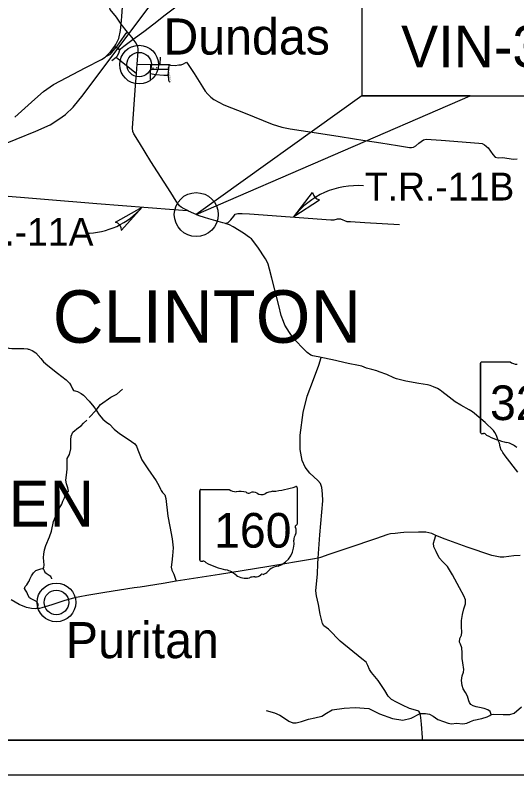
# Model space of a CAD drawing. Extents: x -22 to 431, y -18 to 160.
# Drawn here: x -18.95 to -17.504, y 22.164 to 24.356 of the extents above; entities that cross this region are included whole.
import ezdxf

# ---------------------------------------------------------------- set-up
doc = ezdxf.new("R2010")
doc.units = 0
for name, color, linetype in [('GM_X_Adjacent_County', 7, 'Continuous'), ('GM_X_Adjacent_County_Text', 7, 'Continuous'), ('GM_X_Airport_Location_Class_2', 7, 'Continuous'), ('GM_X_County_Road', 7, 'Continuous'), ('GM_X_County_Road_Text', 7, 'Continuous'), ('GM_X_County_ROW', 7, 'Continuous'), ('GM_X_County_Subdivision', 7, 'Continuous'), ('GM_X_Interstate_Location', 7, 'Continuous'), ('GM_X_Minor_Lake', 7, 'Continuous'), ('GM_X_Minor_River_Text', 7, 'Continuous'), ('GM_X_Section', 7, 'Continuous'), ('GM_X_State_Location', 7, 'Continuous'), ('GM_X_Township_Road', 7, 'Continuous'), ('GM_X_Township_ROW', 7, 'Continuous')]:
    doc.layers.add(name, color=color, linetype=linetype)

msp = doc.modelspace()

# ---------------------------------------------------------------- linework, layer by layer
at = {"layer": 'GM_X_Adjacent_County'}
for p, q in [((-18.147, 23.7739), (-18.0927, 23.8445)), ((-18.0927, 23.8445), (-18.0928, 23.8444)), ((-18.073, 23.8229), (-18.147, 23.7739)), ((-18.073, 23.8229), (-18.073, 23.8229)), ((-18.661, 23.7592), (-18.5836, 23.8025)), ((-18.5836, 23.8025), (-18.643, 23.7362)), ((-18.661, 23.7592), (-18.661, 23.7592)), ((-18.643, 23.7362), (-18.6429, 23.7362))]:
    msp.add_line(p, q, dxfattribs=at)
msp.add_circle((-18.428, 23.781), 0.0633, dxfattribs=at)
for centre, radius, start, end in [((-17.9649, 23.636), 0.2284, 85.1742, 142.8783), ((-18.0664, 23.8487), 0.0266, 189.1962, 255.8769), ((-18.7473, 23.9426), 0.2154, 269.9591, 319.4479), ((-18.6695, 23.7339), 0.0266, 4.907, 71.5877)]:
    msp.add_arc(centre, radius, start, end, dxfattribs=at)
at = {"layer": 'GM_X_Adjacent_County_Text'}
for points in [[(-18.6444, 24.3307), (-18.6582, 24.3505), (-18.6757, 24.3727), (-18.6795, 24.385), (-18.6947, 24.445), (-18.6988, 24.4658), (-18.6979, 24.4791), (-18.6949, 24.4873), (-18.6703, 24.5281), (-18.6438, 24.5713), (-18.6356, 24.5844), (-18.6327, 24.5869), (-18.6291, 24.5876)], [(-18.6094, 24.287), (-18.5787, 24.3092), (-18.5505, 24.3315), (-18.518, 24.3574), (-18.4605, 24.3995), (-18.4433, 24.4142), (-18.4205, 24.4347), (-18.4028, 24.4517), (-18.3964, 24.4589), (-18.3859, 24.4643), (-18.3672, 24.4727), (-18.3366, 24.484), (-18.3213, 24.4913), (-18.31, 24.5002), (-18.2964, 24.5094), (-18.2833, 24.5163), (-18.2703, 24.5193), (-18.2595, 24.5215), (-18.252, 24.5266), (-18.2431, 24.5343), (-18.2431, 24.5343)]]:
    msp.add_lwpolyline(points, dxfattribs=at)
at = {"layer": 'GM_X_Airport_Location_Class_2'}
for p, q in [((-17.608, 23.3522), (-17.608, 23.152)), ((-17.608, 23.152), (-17.608, 23.3522)), ((-17.608, 23.152), (-17.608, 23.3522)), ((-17.6052, 23.3556), (-17.5232, 23.3556)), ((-18.4173, 22.9841), (-18.4173, 22.784)), ((-18.4173, 22.784), (-18.4173, 22.9841)), ((-18.4173, 22.784), (-18.4173, 22.9841)), ((-18.4146, 22.9876), (-18.3325, 22.9876)), ((-18.1372, 22.9925), (-18.1372, 22.8878)), ((-18.1372, 22.8879), (-18.1372, 22.8878))]:
    msp.add_line(p, q, dxfattribs=at)
for centre, major_axis, start_param, end_param in [((-17.6048, 23.3526), (0.00325, 0), 1.712693, 3.28349), ((-17.5036, 23.3788), (0.0315, 0), 4.042523, 4.731795), ((-17.6047, 23.1516), (0.00327, 0), 3.00124, 4.508301), ((-17.6042, 23.1721), (0.025, 0), 4.665946, 4.897461), ((-17.5991, 23.1405), (0.00901, 0), 0.519207, 1.627899), ((-17.4854, 23.3203), (0.2145, 0), 4.195997, 4.488961), ((-17.5493, 23.0621), (0.0671, 0), 0.823519, 1.323587), ((-18.237, 23.2604), (0.2971, 0), 4.814394, 5.042369), ((-18.1403, 22.993), (0.00312, 0), 6.141152, 7.989035), ((-18.4141, 22.9845), (0.00325, 0), 1.712693, 3.28349), ((-18.313, 23.0108), (0.0315, 0), 4.042523, 4.731795), ((-18.3026, 22.8752), (0.113, 0), 1.404758, 1.657858), ((-18.2769, 22.9856), (0.00908, 0), 3.836095, 5.185415), ((-18.2636, 22.9625), (0.0189, 0), 0.950623, 2.079405), ((-18.2392, 22.9942), (0.0227, 0), 4.081561, 5.145723), ((-18.1991, 22.9264), (0.0598, 0), 1.699011, 2.107814), ((-18.1405, 22.8874), (0.00334, 0), 5.05454, 6.418171), ((-18.1379, 22.8802), (0.00483, 0), 1.883978, 3.671073), ((-18.1686, 22.8669), (0.029, 0), 5.934695, 6.695948), ((-18.2203, 22.8307), (0.0743, 0), 5.101752, 6.440018), ((-18.126, 22.844), (0.0211, 0), 2.387724, 3.262537), ((-18.4141, 22.7836), (0.00327, 0), 3.00124, 4.508301), ((-18.4136, 22.804), (0.025, 0), 4.665946, 4.897461), ((-18.4085, 22.7725), (0.00901, 0), 0.519207, 1.627899), ((-18.2947, 22.9523), (0.2145, 0), 4.195997, 4.488961), ((-18.3587, 22.6941), (0.0671, 0), 0.823519, 1.323587), ((-18.189, 22.7278), (0.0407, 0), 1.647645, 2.488434), ((-18.2861, 22.7715), (0.0426, 0), 4.026481, 4.996735), ((-18.2615, 22.7023), (0.035, 0), 1.495662, 1.94098), ((-18.2584, 22.7565), (0.0227, 0), 4.691044, 5.507374), ((-18.2378, 22.7371), (0.00639, 0), 1.147584, 2.315152), ((-18.2406, 22.7646), (0.024, 0), 4.937069, 5.64225)]:
    msp.add_ellipse(centre, major_axis=major_axis, ratio=0.941176, start_param=start_param, end_param=end_param, dxfattribs=at)
at = {"layer": 'GM_X_County_Road'}
for points in [[(-18.7368, 23.1956), (-18.7165, 23.2163), (-18.7038, 23.2325), (-18.6742, 23.2537), (-18.6565, 23.2625), (-18.641, 23.2771)], [(-18.226, 22.3501), (-18.2027, 22.343), (-18.1871, 22.3359), (-18.1759, 22.3293), (-18.1611, 22.3189), (-18.1497, 22.314), (-18.1399, 22.3139), (-18.1246, 22.3183), (-18.1046, 22.3248), (-18.0857, 22.3285), (-18.0654, 22.3335), (-18.0522, 22.3417), (-18.0362, 22.3513), (-18.0014, 22.356), (-17.9696, 22.3582), (-17.9304, 22.3557), (-17.8997, 22.3401), (-17.8618, 22.3264), (-17.8325, 22.322), (-17.8081, 22.3272), (-17.7824, 22.341)]]:
    msp.add_lwpolyline(points, dxfattribs=at)
at = {"layer": 'GM_X_County_ROW'}
for points in [[(-18.6437, 24.3408), (-18.6429, 24.3521), (-18.6358, 24.4504), (-18.6304, 24.5455), (-18.6291, 24.5876), (-18.6255, 24.5996), (-18.6301, 24.6742), (-18.6316, 24.7474), (-18.6286, 24.8016), (-18.6221, 24.8538), (-18.6152, 24.8875), (-18.6078, 24.9365), (-18.6025, 25.0054), (-18.6043, 25.0555), (-18.6064, 25.095), (-18.6068, 25.1047), (-18.6031, 25.1591), (-18.5941, 25.2784), (-18.5867, 25.3715), (-18.5863, 25.3761)], [(-18.9514, 24.0615), (-18.8933, 24.1137), (-18.8687, 24.1361), (-18.8397, 24.1564), (-18.7467, 24.2052), (-18.7012, 24.2281), (-18.6906, 24.2354), (-18.689, 24.2371), (-18.6755, 24.2507), (-18.6627, 24.2673), (-18.6596, 24.2713), (-18.6507, 24.2893), (-18.6461, 24.3116), (-18.6444, 24.3307), (-18.6437, 24.3408)], [(-17.5011, 23.0376), (-17.5371, 23.0846), (-17.5437, 23.094), (-17.5463, 23.0979), (-17.5483, 23.101), (-17.5514, 23.1107), (-17.554, 23.1212), (-17.5571, 23.1292), (-17.5625, 23.1432), (-17.5666, 23.1523), (-17.5711, 23.1574), (-17.5949, 23.1806), (-17.6254, 23.2072), (-17.6316, 23.2118), (-17.6409, 23.2173), (-17.6655, 23.2305), (-17.6816, 23.2407), (-17.6991, 23.2541), (-17.7196, 23.2705), (-17.7243, 23.2743), (-17.732, 23.2787), (-17.7443, 23.284), (-17.7537, 23.2878), (-17.7609, 23.2897), (-17.7864, 23.2932), (-17.8234, 23.3), (-17.8503, 23.3072), (-17.8578, 23.3096), (-17.8781, 23.3191), (-17.9009, 23.3275), (-17.9069, 23.3299), (-17.9212, 23.3338), (-17.9372, 23.3381), (-17.9509, 23.3431), (-17.9598, 23.3457), (-17.99, 23.3514), (-18.0347, 23.3614), (-18.0676, 23.3685), (-18.0712, 23.3693), (-18.0873, 23.3727), (-18.092, 23.3733), (-18.0973, 23.3751), (-18.1081, 23.3828), (-18.1233, 23.3984), (-18.1376, 23.4135), (-18.1486, 23.4251), (-18.1592, 23.4406), (-18.1723, 23.4614), (-18.1764, 23.4723), (-18.1829, 23.4897), (-18.1899, 23.5182), (-18.2101, 23.597), (-18.2166, 23.6235), (-18.2205, 23.6376), (-18.2232, 23.6444), (-18.2278, 23.6527), (-18.2506, 23.6871), (-18.2691, 23.7106), (-18.2741, 23.7148), (-18.2919, 23.7271), (-18.3216, 23.7454), (-18.3319, 23.7509), (-18.344, 23.7555), (-18.3509, 23.7571), (-18.3918, 23.7684), (-18.4044, 23.772), (-18.4191, 23.777), (-18.4504, 23.7911), (-18.4534, 23.7926), (-18.4626, 23.797), (-18.4718, 23.8023), (-18.4761, 23.806), (-18.4859, 23.8193), (-18.5017, 23.8443), (-18.5592, 23.9341), (-18.592, 23.9877), (-18.6078, 24.0138), (-18.6111, 24.0205), (-18.6115, 24.0302), (-18.6037, 24.1395), (-18.6002, 24.1876), (-18.5983, 24.2144), (-18.5956, 24.2514), (-18.5951, 24.259), (-18.5968, 24.2653), (-18.6012, 24.2758), (-18.6094, 24.287), (-18.613, 24.2918), (-18.6258, 24.3076), (-18.6444, 24.3307)], [(-17.4944, 22.7966), (-17.5124, 22.7962), (-17.5407, 22.792), (-17.5519, 22.7922), (-17.576, 22.7974), (-17.647, 22.8208), (-17.7099, 22.8446), (-17.7368, 22.8552), (-17.7485, 22.8602), (-17.7575, 22.8626), (-17.7658, 22.8641), (-17.7872, 22.8642), (-17.8296, 22.8631), (-17.8391, 22.8629), (-17.8547, 22.8607), (-17.8674, 22.8593), (-17.876, 22.8572), (-17.911, 22.8451), (-17.9884, 22.819), (-18.0454, 22.7996), (-18.0695, 22.7913), (-18.0761, 22.7898), (-18.087, 22.7875), (-18.2243, 22.7648), (-18.3609, 22.7426), (-18.4855, 22.7228), (-18.5232, 22.7167), (-18.5896, 22.7061), (-18.607, 22.7034)], [(-18.607, 22.7034), (-18.6071, 22.7034), (-18.6918, 22.6903), (-18.7439, 22.6816), (-18.7638, 22.678), (-18.7787, 22.6747), (-18.7882, 22.672), (-18.8065, 22.6669), (-18.8446, 22.6546), (-18.873, 22.6464), (-18.88, 22.6442), (-18.8853, 22.6438), (-18.891, 22.6428), (-18.9029, 22.6439), (-18.9171, 22.6472), (-18.9389, 22.6555), (-18.9615, 22.6688)]]:
    msp.add_lwpolyline(points, dxfattribs=at)
at = {"layer": 'GM_X_Minor_Lake'}
for points in [[(-17.9503, 24.1237), (-16.7003, 24.1237), (-16.7003, 24.4037), (-17.9503, 24.4037)], [(-17.9503, 24.1237), (-18.428, 23.781), (-17.6378, 24.1237)]]:
    msp.add_lwpolyline(points, close=True, dxfattribs=at)
at = {"layer": 'GM_X_Minor_River_Text'}
for points in [[(-18.5983, 24.2144), (-18.5594, 24.2141), (-18.532, 24.214), (-18.5265, 24.214), (-18.5076, 24.2139), (-18.5065, 24.2136), (-18.5022, 24.2124), (-18.489, 24.2114), (-18.4777, 24.2125), (-18.4714, 24.2133), (-18.4644, 24.216), (-18.4584, 24.2196), (-18.4561, 24.2204), (-18.451, 24.2136), (-18.434, 24.1875), (-18.4102, 24.1491), (-18.402, 24.137), (-18.3944, 24.1285), (-18.3859, 24.1193), (-18.3771, 24.1125), (-18.3483, 24.098), (-18.2871, 24.0734), (-18.2092, 24.0419), (-18.1813, 24.0329), (-18.1573, 24.0279), (-18.0937, 24.0187), (-18.0128, 24.006), (-17.9418, 23.9949)], [(-17.9418, 23.9949), (-17.9408, 23.9947), (-17.8956, 23.9877), (-17.8481, 23.9801), (-17.8134, 23.9746), (-17.8072, 23.9746), (-17.8017, 23.9757), (-17.7947, 23.9794), (-17.7864, 23.9866), (-17.7798, 23.9916), (-17.773, 23.9965), (-17.7653, 23.9988), (-17.7216, 23.9956), (-17.6135, 23.9868), (-17.6038, 23.986), (-17.5966, 23.9817), (-17.5924, 23.9781)], [(-17.5924, 23.9781), (-17.5911, 23.977), (-17.5864, 23.973), (-17.5725, 23.9538), (-17.566, 23.9464), (-17.5577, 23.9443), (-17.5454, 23.9453), (-17.5257, 23.9424), (-17.5142, 23.9405), (-17.503, 23.9417)], [(-19.1218, 23.8451), (-19.1217, 23.8451), (-19.0169, 23.8377), (-18.7149, 23.813), (-18.641, 23.8071)], [(-18.641, 23.8071), (-18.6409, 23.8071), (-18.4928, 23.7953), (-18.4534, 23.7926)], [(-18.344, 23.7555), (-18.336, 23.7581), (-18.3283, 23.7657), (-18.32, 23.7767), (-18.3155, 23.7816), (-18.3083, 23.7838), (-18.2958, 23.7838), (-18.2746, 23.7833), (-18.0396, 23.7659), (-18.0307, 23.7658), (-18.0209, 23.7684), (-18.0118, 23.7681), (-17.9934, 23.7608), (-17.9857, 23.7605)], [(-17.9857, 23.7605), (-17.9835, 23.7605), (-17.9417, 23.758), (-17.842, 23.7519)], [(-19.0652, 23.4582), (-19.0371, 23.4357), (-19.0111, 23.4191), (-18.9829, 23.4022), (-18.9742, 23.3974), (-18.9683, 23.395), (-18.9592, 23.3943), (-18.9376, 23.3944), (-18.9249, 23.3944), (-18.9136, 23.393), (-18.9135, 23.3929)], [(-18.9135, 23.3929), (-18.9107, 23.3926), (-18.9015, 23.3886), (-18.8908, 23.3821), (-18.8756, 23.3658), (-18.868, 23.3562), (-18.8559, 23.3451), (-18.8278, 23.323), (-18.8033, 23.3038), (-18.7932, 23.2943), (-18.7882, 23.2862), (-18.7846, 23.2779), (-18.7818, 23.2735), (-18.7782, 23.2722), (-18.7772, 23.272)], [(-18.0773, 23.0135), (-18.0773, 23.0135), (-18.1001, 23.0344), (-18.1138, 23.0516), (-18.123, 23.0707), (-18.1279, 23.1028), (-18.1279, 23.1446), (-18.1196, 23.2095), (-18.1079, 23.2573), (-18.0898, 23.3048), (-18.0746, 23.346), (-18.0676, 23.3685)], [(-18.7772, 23.272), (-18.7772, 23.272), (-18.77, 23.2702), (-18.7594, 23.2647), (-18.7533, 23.2594), (-18.7368, 23.2424), (-18.7231, 23.2258), (-18.7165, 23.2163), (-18.708, 23.2033), (-18.697, 23.1907), (-18.6856, 23.1808), (-18.6782, 23.1758), (-18.6647, 23.162), (-18.6493, 23.1492), (-18.6239, 23.1328), (-18.6049, 23.1194), (-18.6002, 23.113), (-18.5961, 23.102), (-18.5849, 23.0728), (-18.5671, 23.0467), (-18.5439, 23.0123), (-18.5355, 22.9995), (-18.5309, 22.9885), (-18.5287, 22.9845), (-18.5248, 22.9793)], [(-18.8303, 22.9182), (-18.8262, 22.9282), (-18.8155, 22.9449), (-18.8127, 22.9538), (-18.8076, 22.9635), (-18.8046, 22.9722), (-18.8011, 22.977), (-18.7967, 22.9829), (-18.7983, 22.9922), (-18.8021, 23.0035), (-18.8035, 23.0145), (-18.8017, 23.0289), (-18.8006, 23.046), (-18.8005, 23.0644), (-18.7998, 23.0765), (-18.7938, 23.0881), (-18.7895, 23.1044), (-18.7891, 23.1306), (-18.7886, 23.1414), (-18.7835, 23.1526), (-18.7678, 23.1661), (-18.7597, 23.1716), (-18.753, 23.1787), (-18.743, 23.1874)], [(-18.0761, 22.7898), (-18.0715, 22.8569), (-18.0634, 22.9548), (-18.0635, 22.9749), (-18.0659, 22.9929), (-18.0693, 23.0044), (-18.0773, 23.0135)], [(-18.5248, 22.9793), (-18.5247, 22.9792), (-18.5229, 22.9768), (-18.5188, 22.9724), (-18.5155, 22.9615), (-18.51, 22.9103), (-18.504, 22.8808), (-18.4976, 22.8455), (-18.4948, 22.8192), (-18.4964, 22.7957), (-18.498, 22.778), (-18.5004, 22.7638), (-18.4979, 22.7551), (-18.493, 22.7428), (-18.4855, 22.7228)], [(-18.9102, 22.7223), (-18.9101, 22.7225), (-18.908, 22.729), (-18.9033, 22.7385), (-18.8973, 22.7472), (-18.8903, 22.7537), (-18.8822, 22.7569), (-18.8762, 22.7583), (-18.8699, 22.7595), (-18.869, 22.7596), (-18.8671, 22.7625), (-18.866, 22.7705), (-18.8672, 22.7794), (-18.868, 22.7909), (-18.8678, 22.8008), (-18.8658, 22.8135), (-18.8617, 22.826), (-18.8508, 22.8507), (-18.8456, 22.8674), (-18.8399, 22.8949), (-18.8303, 22.9182), (-18.8303, 22.9182)], [(-17.5772, 22.338), (-17.5802, 22.3467), (-17.5876, 22.352), (-17.598, 22.3558), (-17.6115, 22.3582), (-17.6213, 22.3604), (-17.6298, 22.3636), (-17.6367, 22.3675), (-17.6405, 22.3726), (-17.6422, 22.3772), (-17.6435, 22.3844), (-17.6457, 22.3914), (-17.6519, 22.402), (-17.6579, 22.4122), (-17.6615, 22.4215), (-17.6629, 22.4361), (-17.6612, 22.4501), (-17.6573, 22.4602), (-17.6564, 22.4681), (-17.6593, 22.4876), (-17.6609, 22.5), (-17.6615, 22.5164), (-17.6624, 22.5305), (-17.666, 22.5409), (-17.6685, 22.5469), (-17.6676, 22.5572), (-17.6631, 22.5669), (-17.6618, 22.5762), (-17.663, 22.5913), (-17.6627, 22.609), (-17.6603, 22.6264), (-17.656, 22.6427), (-17.6516, 22.6579), (-17.6514, 22.6693), (-17.6562, 22.6808), (-17.6686, 22.7035), (-17.689, 22.7408), (-17.7033, 22.7656), (-17.7174, 22.779), (-17.7271, 22.7901), (-17.7366, 22.8081), (-17.7427, 22.8219), (-17.7435, 22.8331), (-17.7411, 22.8424), (-17.7368, 22.8552)], [(-17.7824, 22.341), (-17.7836, 22.3432), (-17.7866, 22.348), (-17.7955, 22.3508), (-17.8128, 22.3556), (-17.8329, 22.3652), (-17.8501, 22.3735), (-17.8647, 22.3816), (-17.8744, 22.391), (-17.8845, 22.4073), (-17.9036, 22.4366), (-17.9224, 22.4593), (-17.9285, 22.4681), (-17.9331, 22.4793), (-17.9384, 22.4888), (-17.9506, 22.4989), (-18.0127, 22.5501), (-18.0239, 22.5608), (-18.0349, 22.5731), (-18.0471, 22.584), (-18.0596, 22.5939), (-18.0638, 22.6005), (-18.0703, 22.6277), (-18.0756, 22.6552), (-18.081, 22.6806), (-18.0827, 22.6954), (-18.0788, 22.7445), (-18.0774, 22.7733), (-18.0761, 22.7898)], [(-18.869, 22.7596), (-18.8667, 22.7536), (-18.8644, 22.7489), (-18.8604, 22.7458), (-18.8547, 22.7425), (-18.8492, 22.7379), (-18.8473, 22.7351), (-18.8456, 22.7307), (-18.8454, 22.7294)], [(-18.8853, 22.6438), (-18.8853, 22.6468), (-18.8842, 22.6534), (-18.8841, 22.6566), (-18.8863, 22.6612), (-18.8909, 22.6657), (-18.8981, 22.6689), (-18.9055, 22.6725), (-18.9084, 22.6753), (-18.9125, 22.6814), (-18.9169, 22.6908), (-18.9207, 22.6967), (-18.9236, 22.7022), (-18.921, 22.7079), (-18.9167, 22.7124), (-18.9104, 22.7216), (-18.9102, 22.7223)], [(-17.7824, 22.341), (-17.7673, 22.3408), (-17.7552, 22.3394), (-17.7444, 22.3332), (-17.7309, 22.3241), (-17.7152, 22.3177), (-17.7013, 22.3129), (-17.6919, 22.3114), (-17.6779, 22.3128), (-17.6593, 22.3115), (-17.6478, 22.3135), (-17.637, 22.3177), (-17.6272, 22.3215), (-17.6043, 22.3271), (-17.5892, 22.3315), (-17.5815, 22.3354), (-17.5772, 22.338), (-17.5716, 22.3396), (-17.5434, 22.338), (-17.524, 22.3384), (-17.5111, 22.3425), (-17.4902, 22.3602)], [(-17.7752, 22.2642), (-17.7755, 22.2718), (-17.7785, 22.3101), (-17.7807, 22.3296), (-17.7824, 22.341)]]:
    msp.add_lwpolyline(points, dxfattribs=at)
at = {"layer": 'GM_X_Section'}
for p, q in [((-21.8776, 22.2642), (-15.0776, 22.2642)), ((-15.0776, 22.2642), (-21.8776, 22.2642)), ((-21.9776, 22.1642), (-14.9776, 22.1642))]:
    msp.add_line(p, q, dxfattribs=at)
at = {"layer": 'GM_X_State_Location'}
msp.add_lwpolyline([(-19.4199, 23.4073), (-19.3673, 23.5169), (-19.3087, 23.6398), (-19.2532, 23.7554), (-19.2299, 23.8014), (-19.2152, 23.831), (-19.1994, 23.855), (-19.1872, 23.8706), (-19.1662, 23.891), (-19.142, 23.9104), (-19.1189, 23.9268), (-19.0934, 23.9403), (-19.0768, 23.9482), (-19.0048, 23.9755), (-18.8909, 24.0211), (-18.849, 24.0399), (-18.8239, 24.0562), (-18.8054, 24.0699), (-18.7831, 24.0912), (-18.7541, 24.1266), (-18.5498, 24.3984)], dxfattribs=at)
at = {"layer": 'GM_X_Township_Road'}
for centre, radius in [((-18.5927, 24.2135), 0.0558), ((-18.5927, 24.2135), 0.0354), ((-18.8311, 22.6616), 0.0558), ((-18.8311, 22.6616), 0.0354)]:
    msp.add_circle(centre, radius, dxfattribs=at)
at = {"layer": 'GM_X_Township_ROW'}
for points in [[(-18.689, 24.2371), (-18.6755, 24.2434), (-18.6586, 24.2641), (-18.6563, 24.267), (-18.6362, 24.296), (-18.6296, 24.3044), (-18.6258, 24.3076)], [(-18.6627, 24.2673), (-18.6586, 24.2641), (-18.6479, 24.2559)], [(-18.6564, 24.2381), (-18.6564, 24.2382), (-18.6515, 24.2463), (-18.6491, 24.2533), (-18.6479, 24.2559), (-18.6464, 24.259), (-18.6368, 24.267), (-18.6094, 24.287)], [(-18.6711, 24.225), (-18.6584, 24.2347), (-18.6564, 24.2381)], [(-18.6584, 24.2347), (-18.6002, 24.1876)], [(-18.532, 24.214), (-18.5315, 24.2354)], [(-18.5599, 24.1813), (-18.56, 24.1876), (-18.5601, 24.1912), (-18.5592, 24.2006), (-18.5586, 24.2063), (-18.5588, 24.2105), (-18.5594, 24.2141)], [(-18.56, 24.1876), (-18.5451, 24.1853), (-18.5216, 24.1835), (-18.5086, 24.183), (-18.5069, 24.2001), (-18.5065, 24.2136)], [(-18.5592, 24.2006), (-18.5069, 24.2001)], [(-18.5598, 24.1703), (-18.5599, 24.1813), (-18.5599, 24.1813)], [(-18.5043, 24.1616), (-18.5068, 24.1675), (-18.5072, 24.1739), (-18.5086, 24.183)]]:
    msp.add_lwpolyline(points, dxfattribs=at)

# ---------------------------------------------------------------- texts
at = {"layer": 'GM_X_Adjacent_County'}
for s, height, p in [('Dundas', 0.10417, (-18.5227, 24.2426)), ('T.R.-11B', 0.08049, (-17.9417, 23.8214)), ('T.R.-11A', 0.08049, (-19.1548, 23.6907)), ('Puritan', 0.10417, (-18.804, 22.5008))]:
    msp.add_text(s, height=height, rotation=0, dxfattribs=at).set_placement(p)
at = {"layer": 'GM_X_Airport_Location_Class_2'}
for s, p in [('324', (-17.5809, 23.1878)), ('160', (-18.3765, 22.8197))]:
    msp.add_text(s, height=0.1, dxfattribs=at).set_placement(p)
at = {"layer": 'GM_X_County_Road_Text'}
msp.add_text('CLINTON', height=0.15152, rotation=0, dxfattribs=at).set_placement((-18.8418, 23.4109))
at = {"layer": 'GM_X_County_Subdivision'}
for s, rotation, p in [('ALLEY', 0, (-18.5557, 24.2018)), ('ST', 356.1879, (-18.5131, 24.2014)), ('A', 275.8454, (-18.5082, 24.1911)), ('L', 275.8302, (-18.5077, 24.1869)), ('L', 275.8302, (-18.5074, 24.1836)), ('E', 275.8581, (-18.5071, 24.1803)), ('Y', 275.8454, (-18.5067, 24.177)), ('S', 276.0332, (-18.5062, 24.1716)), ('T', 301.1952, (-18.5051, 24.1661))]:
    msp.add_text(s, height=0.00473, rotation=rotation, dxfattribs=at).set_placement(p)
at = {"layer": 'GM_X_Interstate_Location'}
msp.add_text('HAMDEN', height=0.13258, rotation=0, dxfattribs=at).set_placement((-19.4913, 22.8802))
at = {"layer": 'GM_X_Section'}
msp.add_text('VIN-324-3.21', height=0.12, dxfattribs=at).set_placement((-17.8374, 24.206))

doc.saveas('drawing.dxf')
